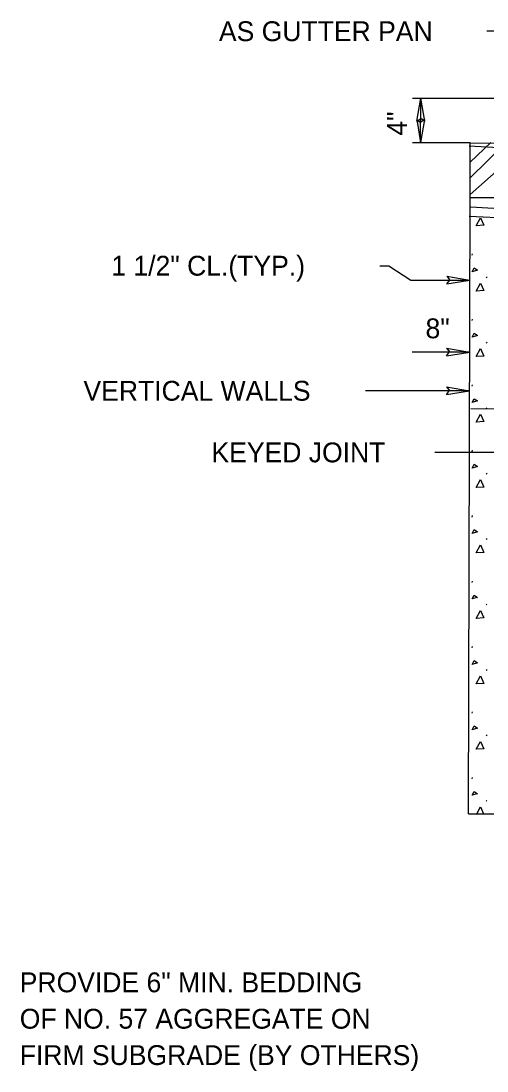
# Model space of a CAD drawing. Extents: x 4.74 to 11.91, y -5.26 to 4.54.
# Drawn here: x 4.744 to 6.154, y -2.087 to 1.088 of the extents above; entities that cross this region are included whole.
import ezdxf

# ---------------------------------------------------------------- set-up
doc = ezdxf.new("R2010")
doc.units = 0
for name, color, linetype in [('DETL-DIMS', 7, 'Continuous'), ('DETL-LINE', 7, 'Continuous'), ('DETL-NOTE', 7, 'Continuous'), ('DETL-PATT', 7, 'Continuous')]:
    doc.layers.add(name, color=color, linetype=linetype)

msp = doc.modelspace()

# ---------------------------------------------------------------- linework, layer by layer
at = {"layer": 'DETL-DIMS'}
for p, q in [((6.4044, 1.0569), (6.1534, 1.0569)), ((6.3174, 0.8531), (5.9287, 0.8531)), ((5.9418, 0.7846), (5.9535, 0.8546)), ((5.9527, 0.7201), (5.9535, 0.8546)), ((5.9652, 0.7846), (5.9535, 0.8546)), ((5.941, 0.7901), (5.9527, 0.7201)), ((5.941, 0.7901), (5.9527, 0.7813)), ((5.9418, 0.7846), (5.9535, 0.7933)), ((5.9644, 0.7901), (5.9527, 0.7201)), ((5.9644, 0.7901), (5.9527, 0.7813)), ((5.9652, 0.7846), (5.9535, 0.7933)), ((6.1031, 0.7198), (5.9287, 0.7198)), ((5.8293, 0.3478), (5.8564, 0.3476)), ((5.8564, 0.3476), (5.9232, 0.3037)), ((5.9232, 0.3037), (6.102, 0.3037)), ((6.0319, 0.2925), (6.0408, 0.3041)), ((6.0319, 0.2925), (6.102, 0.3037)), ((6.0321, 0.3158), (6.102, 0.3037)), ((6.0321, 0.3158), (6.0408, 0.3041)), ((6.0315, 0.0988), (6.1014, 0.0867)), ((6.0315, 0.0988), (6.0402, 0.0871)), ((6.1014, 0.0867), (5.9268, 0.0867)), ((6.0313, 0.0755), (6.0402, 0.0871)), ((6.0313, 0.0755), (6.1014, 0.0867)), ((6.1011, -0.0304), (5.7865, -0.0304)), ((6.031, -0.0417), (6.0399, -0.03)), ((6.031, -0.0417), (6.1011, -0.0304)), ((6.0312, -0.0183), (6.1011, -0.0304)), ((6.0312, -0.0183), (6.0399, -0.03)), ((6.4998, -0.2168), (5.9955, -0.2168))]:
    msp.add_line(p, q, dxfattribs=at)
at = {"layer": 'DETL-LINE'}
for p, q in [((6.348, 0.6952), (6.1, 0.709)), ((6.1027, 0.5541), (6.1031, 0.7198)), ((6.1031, 0.7198), (6.3472, 0.7166)), ((6.0977, -1.3098), (6.1027, 0.5541)), ((6.1027, 0.5541), (6.3469, 0.5541)), ((6.3527, 0.5109), (6.1046, 0.5247)), ((6.348, 0.4833), (6.1, 0.4971)), ((6.1042, -0.0844), (6.1844, -0.0846)), ((6.0977, -1.3098), (8.612, -1.3098))]:
    msp.add_line(p, q, dxfattribs=at)
at = {"layer": 'DETL-PATT'}
for p, q in [((6.1025, 0.6132), (6.209, 0.717)), ((6.1027, 0.6607), (6.1647, 0.7203)), ((6.2762, 0.7181), (6.1027, 0.5632)), ((6.1084, 0.3796), (6.11, 0.3839)), ((6.1514, 0.3141), (6.1535, 0.3114)), ((6.1084, 0.1817), (6.11, 0.186)), ((6.1514, 0.1162), (6.1535, 0.1135)), ((6.1084, -0.0163), (6.11, -0.012)), ((6.1514, -0.0817), (6.1535, -0.0844)), ((6.1084, -0.2142), (6.11, -0.2099)), ((6.1514, -0.2797), (6.1535, -0.2823)), ((6.1084, -0.4121), (6.11, -0.4078)), ((6.1514, -0.4776), (6.1535, -0.4803)), ((6.1084, -0.61), (6.11, -0.6057)), ((6.1514, -0.6755), (6.1535, -0.6782)), ((6.1084, -0.8079), (6.11, -0.8036)), ((6.1514, -0.8734), (6.1535, -0.8761)), ((6.1084, -1.0058), (6.11, -1.0015)), ((6.1514, -1.0713), (6.1535, -1.074)), ((6.1084, -1.2038), (6.11, -1.1995)), ((6.1514, -1.2692), (6.1535, -1.2719))]:
    msp.add_line(p, q, dxfattribs=at)
for points in [[(6.1213, 0.4687), (6.1342, 0.4928), (6.1438, 0.4703), (6.1213, 0.4687)], [(6.109, 0.3297), (6.1149, 0.3415), (6.1245, 0.3345), (6.109, 0.3297)], [(6.1213, 0.2708), (6.1342, 0.2949), (6.1438, 0.2724), (6.1213, 0.2708)], [(6.109, 0.1317), (6.1149, 0.1436), (6.1245, 0.1366), (6.109, 0.1317)], [(6.1213, 0.0729), (6.1342, 0.097), (6.1438, 0.0745), (6.1213, 0.0729)], [(6.109, -0.0662), (6.1149, -0.0544), (6.1245, -0.0613), (6.109, -0.0662)], [(6.1213, -0.1251), (6.1342, -0.1009), (6.1438, -0.1235), (6.1213, -0.1251)], [(6.109, -0.2641), (6.1149, -0.2523), (6.1245, -0.2593), (6.109, -0.2641)], [(6.1213, -0.323), (6.1342, -0.2988), (6.1438, -0.3214), (6.1213, -0.323)], [(6.109, -0.462), (6.1149, -0.4502), (6.1245, -0.4572), (6.109, -0.462)], [(6.1213, -0.5209), (6.1342, -0.4967), (6.1438, -0.5193), (6.1213, -0.5209)], [(6.109, -0.6599), (6.1149, -0.6481), (6.1245, -0.6551), (6.109, -0.6599)], [(6.1213, -0.7188), (6.1342, -0.6947), (6.1438, -0.7172), (6.1213, -0.7188)], [(6.109, -0.8578), (6.1149, -0.846), (6.1245, -0.853), (6.109, -0.8578)], [(6.1213, -0.9167), (6.1342, -0.8926), (6.1438, -0.9151), (6.1213, -0.9167)], [(6.109, -1.0558), (6.1149, -1.0439), (6.1245, -1.0509), (6.109, -1.0558)], [(6.1213, -1.1146), (6.1342, -1.0905), (6.1438, -1.113), (6.1213, -1.1146)], [(6.109, -1.2537), (6.1149, -1.2419), (6.1245, -1.2488), (6.109, -1.2537)], [(6.1228, -1.3098), (6.1342, -1.2884), (6.1433, -1.3098)]]:
    msp.add_lwpolyline(points, dxfattribs=at)

# ---------------------------------------------------------------- texts
at = {"layer": 'DETL-NOTE'}
for s, p in [('AS GUTTER PAN', (5.3429, 1.0269)), ('1 1/2" CL.(TYP.)', (5.0175, 0.3178)), ('8"', (5.9677, 0.1284)), ('VERTICAL WALLS', (4.9333, -0.0604)), ('KEYED JOINT', (5.3204, -0.2468)), ('PROVIDE 6" MIN. BEDDING', (4.7406, -1.8493)), ('OF NO. 57 AGGREGATE ON', (4.7406, -1.9593)), ('FIRM SUBGRADE (BY OTHERS)', (4.7406, -2.0693))]:
    msp.add_text(s, height=0.06, dxfattribs=at).set_placement(p)
msp.add_text('4"', height=0.06, rotation=90, dxfattribs=at).set_placement((5.9114, 0.741))

doc.saveas('drawing.dxf')
